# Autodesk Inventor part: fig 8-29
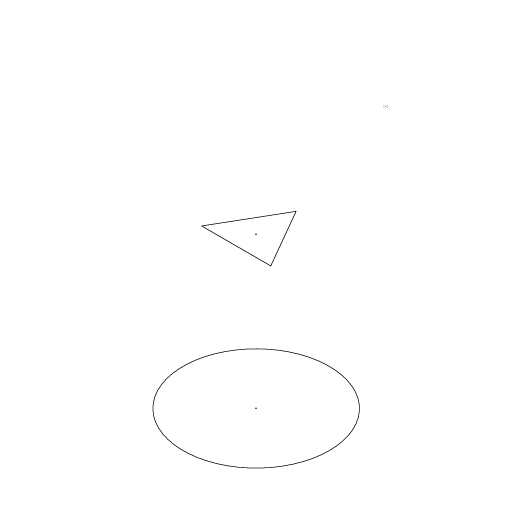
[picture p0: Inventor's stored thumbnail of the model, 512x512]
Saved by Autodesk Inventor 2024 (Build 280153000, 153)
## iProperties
Shininess: 77.0
Angle Display Precision: 2
Document Length Units: 11269
Document Angle Units: 11279
Document Time Units: 11290
Document Mass Units: 11283
Document Length Units Precision: 3
Document Angle Units Precision: 2
Created: 2001-12
Part Number: fig 8-29
Document SubType Name: Modeling
Designer: CADSoft
Density: 1 g/cm^3
Material: Generic
Appearance: Default
Density: 0.0
Volumn: 0.0
Area: 0.0
PropertySet Name: Model Information
Control State: 0
Master: False
Checked Out: False
Author: CADSoft
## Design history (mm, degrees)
workplane "Work Plane3"
workplane "Work Plane4"
sketch "Sketch12"
  geometry: L1 (0, 10.598)-(9.178, -5.299); L2 (9.178, -5.299)-(-9.178, -5.299); L3 (-9.178, -5.299)-(0, 10.598); 1 further point
  constraints: 6 end point, 5 other
workplane "Work Plane5"
body "Solid1"
sketch "Sketch1"
  geometry: C1 r 19.387 at (0, 0); 1 further point
  constraints: 1 centre point, 1 coincident, 1 other
sketch "Sketch2"
  geometry: 1 further point
